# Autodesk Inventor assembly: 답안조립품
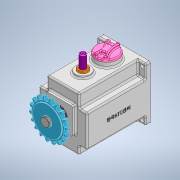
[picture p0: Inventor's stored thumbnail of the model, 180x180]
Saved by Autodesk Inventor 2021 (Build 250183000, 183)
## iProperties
Created: 2022-08
Part Number: 답안조립품
Document SubType Name: Assembly
Designer: Owner
Author: Owner
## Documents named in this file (16)
- C:\Users\Owner\Desktop\720810V1003\답안조립품.iam
- C:\Users\Owner\Desktop\720810V1003\본체.ipt
- C:\Users\Owner\Desktop\720810V1003\멈춤나사 M3.ipt
- C:\Users\Owner\Desktop\720810V1003\메인 축.ipt
- C:\Users\Owner\Desktop\720810V1003\베어링 608.ipt
- C:\Users\Owner\Desktop\720810V1003\베어링 6003.ipt
- C:\Users\Owner\Desktop\720810V1003\볼트 M4 x 10.ipt
- C:\Users\Owner\Desktop\720810V1003\부시.ipt
- C:\Users\Owner\Desktop\720810V1003\상부 캡.ipt
- C:\Users\Owner\Desktop\720810V1003\서브 축.ipt
- C:\Users\Owner\Desktop\720810V1003\스프로킷.ipt
- C:\Users\Owner\Desktop\720810V1003\슬라이더.ipt
- C:\Users\Owner\Desktop\720810V1003\오일 실 8 x 22 x 7.ipt
- C:\Users\Owner\Desktop\720810V1003\오일 실 17 x 32 x 8.ipt
- C:\Users\Owner\Desktop\720810V1003\커버.ipt
- C:\Users\Owner\Desktop\720810V1003\키 5 x 5.ipt
